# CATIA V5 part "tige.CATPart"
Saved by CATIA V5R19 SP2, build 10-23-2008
Part number: tige
Property "LENGTH": 0 mm
Publications: "taille"
Bounding box of the stored display mesh (mm): x -120 to 300, y -15 to 15, z -19.98 to 19.98
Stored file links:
  D:\Dropbox\IAO_2011\MMS_GR2\IAO_2011_1486_jboiteux\tige.CATPart
  C:\iao4\mecanisme a rouleaux.CATProduct
  D:\Dropbox\IAO_2011\MMS_GR2\IAO_2011_1486_jboiteux\bati.CATPart
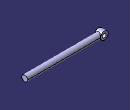
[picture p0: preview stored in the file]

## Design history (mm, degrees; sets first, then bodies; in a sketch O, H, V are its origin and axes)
Parameters
  tailletige = 10 mm {= External.taille}
External parameters (linked from other documents)
  External.taille = 10 mm
Body1 (main body)
  Sketch1 on yz-plane, origin (0, 0, 0), H (0, 1, 0), V (0, 0, 1)
    circle A1 centre (0, 0) radius 15
    radius A1 = 15 {= tailletige*1.5}
  Pad1: profile Sketch1, direction (1, 0, 0), length 300 {= tailletige *30}, opposite side length 100 {= tailletige*10}
  Sketch2 on zx-plane, origin (0, 0, 0), H (-1, 0, 0), V (0, 0, 1)
    circle A1 centre (100, 0) radius 20
    point P1 (100, 0)
    reference projected line E1 (100, -0.75) -> (100, 0.75) from edge [start face of Pad1 | face of Pad1 from Sketch1.A1]
    radius A1 = 20 {= tailletige*2}
    coincidence: P1 H, E1 P1
  Pad2: profile Sketch2, direction (0, -1, 0), length 15 {= tailletige*1.5}, mirrored extent
  Sketch3 on end face of Pad2, origin (-10, -15, 0), H (1, 0, 0), V (0, 0, 1)
    point P1 (-90, 0)
    reference projected circle E1 centre (-90, 0) radius 20 from edge [end face of Pad2 | face of Pad2 from Sketch2.A1]
    concentricity: E1 P1
  Hole1: placed by Sketch3, at (-100, -15, 0) direction (0, 1, 0), diameter 20 {= tailletige *2}, through (limit type 6)
  Point1: type OnPlane, Support end face of Pad1, H 0, V 0, Direction (0, 1, 0)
